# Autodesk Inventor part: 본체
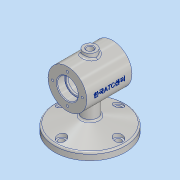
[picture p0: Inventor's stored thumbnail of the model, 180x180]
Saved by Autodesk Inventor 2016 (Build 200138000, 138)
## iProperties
Created: 2018-12
Part Number: 본체
Material: 알루미늄 6061
Document SubType Name: Modeling
Designer: 605-03
Density: 2.7 g/cm^3
Appearance: 알루미늄 - 평지
Mass: 684.823 g
Surface Area: 556.034 cm^2
Volume: 253.638 cm^3
Author: 605-03
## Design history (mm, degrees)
sketch "스케치2"
  geometry: C1 r 30 at (0, 0); 1 further point
  constraints: 1 centre point, 1 coincident
  dimensions: "d0" = 60 diameter of C1
extrude "돌출1" new body sketch "스케치2" stored distance "d1" = 70; taper "d2" = 0 deg
node "작업 평면1"
sketch "스케치3"
  geometry: C1 r 55 at (0, 0); 1 further point
  constraints: 1 centre point, 1 coincident
  dimensions: "d4" = 110 diameter of C1
extrude "돌출2" join sketch "스케치3" distance "d5" = 11; taper "d6" = 0 deg
sketch "스케치5"
  geometry: L1 (55, -75)-(55, -64) reference; L2 (55, -64)-(-55, -64) reference; L3 (55, -64)-(0, -49.263); L4 (0, -49.263)-(0, -64); L5 (0, -64)-(55, -64); 1 further point
  constraints: 6 end point, 1 collinear, 1 midpoint, 1 vertical alignment
  dimensions: "d10" = 75 deg angle of L3 L1
revolve "회전1" sketch "스케치5" stored, may be unused: angle "d11" = 90 deg
sketch "스케치6"
  geometry: C1 r 12 at (0, 0); 1 further point
  constraints: 1 centre point, 1 coincident
  dimensions: "d12" = 24 diameter of C1
extrude "돌출4" join sketch "스케치6" stored distance "d13" = 37; taper "d14" = 0 deg
sketch "스케치7"
  geometry: C1 r 10 at (0, 0); 1 further point
  constraints: 1 centre point, 1 coincident
  dimensions: "d15" = 20 diameter of C1
extrude "돌출5" join sketch "스케치7" distance "d16" = 37; taper "d17" = 0 deg
fillet "모깎기1" dims "d18" = 3
fillet "모깎기2" dims "d19" = 3
sketch "스케치8"
  geometry: L1 (-35, 16)-(-23, 16); L2 (-23, 16)-(-23, 14); L3 (-23, 14)-(-20, 14); L4 (-20, 14)-(-20, 25); L5 (-20, 25)-(20, 25); L6 (20, 25)-(20, 14); L7 (20, 14)-(23, 14); L8 (23, 14)-(23, 16); L9 (23, 16)-(35, 16); L10 (-35, 30)-(-35, -30) reference; L11 (35, -30)-(35, 30) reference; L12 (-35, 0)-(35, 0); L13 (-35, 16)-(-35, 0); L14 (35, 16)-(35, 0); 1 further point
  constraints: 24 end point, 7 perpendicular, 2 midpoint, 2 parallel, 2 point on line, 1 collinear, 1 horizontal
  dimensions: "d20" = 16 distance from line of point (0, 0) L1; "d21" = 12 distance of L1.start L1.end; "d22" = 14 distance from line of point (0, 0) L3; "d23" = 3 distance of L2.end L3.end; "d24" = 25 distance from line of point (0, 0) L5; "d25" = 40 distance of L4.end L5.end; "d26" = 14 distance from line of point (0, 0) L7; "d27" = 3 distance of L6.end L7.end; "d28" = 16 distance from line of point (0, 0) L9
revolve "회전2" sketch "스케치8" stored, may be unused: angle "d29" = 90 deg
fillet "모깎기3" dims "d30" = 0.3
fillet "모깎기4" dims "d31" = 0.3
chamfer "모따기1" distance "d32" = 1; stored, may be unused: second distance "d33" = 2, angle "d34" = 45 deg
fillet "모깎기5" dims "d35" = 3
sketch "스케치9"
  geometry: C1 r 30 at (0, 0) reference; 1 further point
  constraints: 1 vertical alignment
  dimensions: "d36" = 23 distance of C1.centre point (0, 23)
hole "구멍1" sketch "스케치9" at (0, 23) diameter "d37" = 3.459; stored, may be unused: countersink angle "d41" = 90 deg, drill point angle "d43" = 118 deg; dims "d38" = 8, "d39" = 4, "d40" = 2, "d42" = 10
sketch "스케치12"
  geometry: C1 r 10 at (0, 0) reference
hole "구멍2" sketch "스케치12" at (0, 0) diameter "d47" = 10; stored, may be unused: countersink angle "d51" = 90 deg, drill point angle "d53" = 118 deg; dims "d48" = 8, "d49" = 4, "d50" = 2, "d52" = 40
chamfer "모따기2" distance "d54" = 1; stored, may be unused: second distance "d55" = 2, angle "d56" = 45 deg
sketch "스케치15"
  geometry: C1 r 55 at (0, 0) reference; 1 further point
  constraints: 1 vertical alignment
  dimensions: "d66" = 44 distance of C1.centre point (0, -44)
hole "구멍4" sketch "스케치15" at (0, -44) diameter "d67" = 9; stored, may be unused: countersink angle "d71" = 90 deg, drill point angle "d73" = 0 deg; dims "d68" = 8, "d69" = 14, "d70" = 3, "d72" = 10
sketch "스케치17"
  geometry: C1 r 4.5 at (0, 0) reference; C2 r 7 at (0, 0); 1 further point
  constraints: 1 centre point, 1 coincident
  dimensions: "d75" = 14 diameter of C2
extrude "돌출6" cut sketch "스케치17" stored distance "d76" = 37; taper "d77" = 0 deg
node "작업 평면4"
sketch "스케치18"
  geometry: L1 (-35, 30)-(35, 30) reference; L2 (-35, 30)-(-35, -30) reference; 2 further points
  constraints: 1 other
  dimensions: "d81" = 30 distance from line of point (0, 0) L1
feature "엠보싱1" sketch "스케치18" dims "d2" = 0, "d82" = 0.5, "d83" = 0
node "솔리드1"
pattern_circular "원형 패턴1" dims angle "d45" = 360 deg
mirror "대칭1"
pattern_circular "원형 패턴2" dims angle "d79" = 360 deg
other parameters: "d3" = -75
